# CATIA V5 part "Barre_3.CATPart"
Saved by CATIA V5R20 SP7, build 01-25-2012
Part number: Barre_3
Material "Bronze": density 8860 kg/m3, Young's modulus 1.1e+11 Pa, Poisson ratio 0.341, thermal expansion 1.78e-05 1/K
Bounding box of the stored display mesh (mm): x 4 to 6, y 2.165 to 20.189, z 4.766 to 7.187
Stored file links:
  J:\IFMA\IAO\système avant mef\Barre_3.CATPart
  C:\Appli\Dassault Systemes\B20\intel_a\startup\materials\French\Catalog.CATMaterial
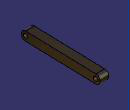
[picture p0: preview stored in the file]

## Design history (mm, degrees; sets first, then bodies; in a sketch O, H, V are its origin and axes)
Body1 (main body), material "Bronze"
  Plane1: stored without definition
  Point1 "Point.D": stored without definition
  Point2 "Point.M": stored without definition
  Sketch1 on Plane1, origin (6, 0, 0), H (0, 1, 0), V (0, 0, 1)
    construction line L1 (3.1651, 6.1875) -> (19.1895, 5.7661)
    point P1 (3.1651, 6.1875)
    point P2 (19.1895, 5.7661)
    line L2 (3.1914, 7.1871) -> (19.2158, 6.7657)
    line L3 (19.1632, 4.7664) -> (3.1388, 5.1878)
    arc A1 centre (19.1895, 5.7661) radius 1 from (19.2158, 6.7657) to (19.1632, 4.7664) cw
    arc A2 centre (3.1651, 6.1875) radius 1 from (3.1388, 5.1878) to (3.1914, 7.1871) cw
    reference projected point E1 (3.1651, 6.1875) from Point1
    reference projected point E2 (19.1895, 5.7661) from Point2
    distance L1 L2 = 1
    tangency: A1 L2, A2 L2, A1 L3, A2 L3
    coincidence: E1 P1, P2 E2
  Pad1: profile Sketch1, direction (-1, 0, 0), length 2
  Sketch2 on start face of Pad1, origin (6, 8.2019, 6.7624), H (0, 1, 0), V (0, 0, 1)
    point P1 (-5.0368, -0.5749)
    reference projected point E1 (-5.0368, -0.5749) from Point3
    coincidence: P1 E1
  Hole1: placed by Sketch2, at (6, 3.1651, 6.1875) direction (-1, 0, 0), diameter 1, through (limit type 3)
  Sketch3 on start face of Pad1, origin (6, 15.894, 5.201), H (0, 1, 0), V (0, 0, 1)
    point P1 (3.2955, 0.5651)
    reference projected point E1 (3.2955, 0.5651) from Point4
    coincidence: P1 E1
  Hole2: placed by Sketch3, at (6, 19.1895, 5.7661) direction (-1, 0, 0), diameter 1, through (limit type 3)
  Point3 "Point.D": stored without definition
  Point4 "Point.M": stored without definition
